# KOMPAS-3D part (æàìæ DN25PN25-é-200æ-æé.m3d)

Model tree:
1. Объединить компоненты:1  (labels: СЕНС DN25PN25-В-200С)
2. Эскиз:1
3. Операция выдавливания:1
     Расстояние 1 = 14
4. Фаска:1
     Угол = 45; Длина 1 = 2; Длина 2 = 2

Referenced files in D:\Савин\!СЕНСОР\3D для заказчика\!Новый перечень\СЕНС\4. СЕНС-В-200С\DN25\: СЕНС DN25PN25-В-200С.a3d
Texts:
  СЕНС DN25PN25-В-200С-СВ
  ООО НПП Сенсор
  СЕНС DN25PN25-В-200С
